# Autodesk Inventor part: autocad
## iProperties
Author: Administrator
Created: 2000-12
Part Number: autocad
Document SubType Name: Modeling
Designer: Administrator
Control State: 0
Master: False
Checked Out: False
PropertySet Name: Design Tracking Control
Shininess: 0.0
PropertySet Name: _Private Model Information
Density: 0.0
Volumn: 0.0
Area: 0.0
PropertySet Name: Model Information
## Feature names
1. Extrusion1
2. Extrusion2
